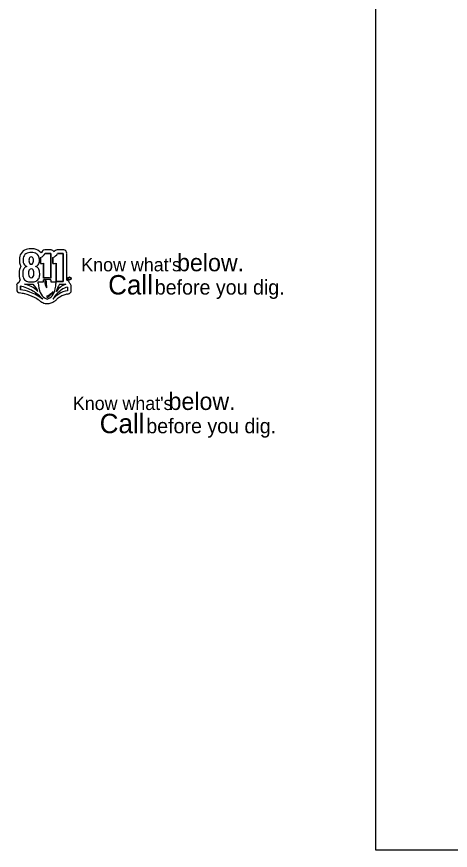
# Model space of a CAD drawing. Extents: x 837 to 1117, y 1316 to 1424.
# Drawn here: x 836.58 to 842.85, y 1398.24 to 1410.3 of the extents above; entities that cross this region are included whole.
import ezdxf

# ---------------------------------------------------------------- set-up
doc = ezdxf.new("R2010")
doc.units = 0
doc.layers.add('0 (Construction)', color=7, linetype='Continuous')
doc.layers.add('Call811-black', color=7, linetype='Continuous')

msp = doc.modelspace()

# ---------------------------------------------------------------- linework, layer by layer
at = {"layer": '0 (Construction)'}
msp.add_lwpolyline([(841.77, 1422.24), (877.77, 1422.24), (877.77, 1398.24), (841.77, 1398.24)], close=True, dxfattribs=at)
at = {"layer": 'Call811-black'}
for p, q in [((836.95, 1406.908), (836.929, 1406.881)), ((837.074, 1406.925), (836.987, 1406.925)), ((836.988, 1406.871), (837.069, 1406.871)), ((837.069, 1406.871), (837.069, 1406.514)), ((837.119, 1406.895), (837.118, 1406.895)), ((837.257, 1406.925), (837.163, 1406.925)), ((837.168, 1406.871), (837.249, 1406.871)), ((837.249, 1406.871), (837.249, 1406.465)), ((837.303, 1406.485), (837.303, 1406.874)), ((836.924, 1406.726), (836.924, 1406.813)), ((836.966, 1406.514), (836.966, 1406.732)), ((837.101, 1406.726), (837.101, 1406.813)), ((837.146, 1406.465), (837.146, 1406.732)), ((836.966, 1406.464), (836.966, 1406.49)), ((837.069, 1406.49), (837.069, 1406.464)), ((836.577, 1406.414), (836.577, 1406.35)), ((836.63, 1406.347), (836.63, 1406.4)), ((836.69, 1406.428), (836.813, 1406.428)), ((836.89, 1406.44), (836.89, 1406.464)), ((836.89, 1406.464), (836.966, 1406.464)), ((837.069, 1406.464), (837.144, 1406.464)), ((837.144, 1406.464), (837.144, 1406.44)), ((837.249, 1406.465), (837.146, 1406.465)), ((837.196, 1406.427), (837.289, 1406.427)), ((837.313, 1406.386), (837.313, 1406.333)), ((837.367, 1406.331), (837.367, 1406.396))]:
    msp.add_line(p, q, dxfattribs=at)
for points in [[(836.95, 1406.908), (836.929, 1406.881)], [(837.074, 1406.925), (836.987, 1406.925)], [(837.069, 1406.514), (837.069, 1406.871), (836.988, 1406.871)], [(837.119, 1406.895), (837.118, 1406.895)], [(837.146, 1406.465), (837.249, 1406.465), (837.249, 1406.871), (837.168, 1406.871)], [(837.257, 1406.925), (837.163, 1406.925)], [(837.303, 1406.485), (837.303, 1406.874)], [(836.924, 1406.813), (836.924, 1406.726)], [(836.966, 1406.732), (836.966, 1406.514)], [(837.101, 1406.813), (837.101, 1406.726)], [(837.146, 1406.732), (837.146, 1406.465)], [(836.89, 1406.44), (836.89, 1406.464), (836.966, 1406.464), (836.966, 1406.49)], [(837.069, 1406.49), (837.069, 1406.464), (837.144, 1406.464), (837.144, 1406.44)], [(836.577, 1406.414), (836.577, 1406.35)], [(836.63, 1406.4), (836.63, 1406.347)], [(836.69, 1406.428), (836.813, 1406.428)], [(837.196, 1406.427), (837.289, 1406.427)], [(837.313, 1406.386), (837.313, 1406.333)], [(837.367, 1406.331), (837.367, 1406.396)], [(837.017, 1406.237), (837.018, 1406.261)]]:
    msp.add_lwpolyline(points, dxfattribs=at)
for radius in [0.0224, 0.0224, 0.0191, 0.0191]:
    msp.add_circle((837.341, 1406.511), radius, dxfattribs=at)
for centre, radius, start, end in [((836.76, 1406.796), 0.143, 99.999, 175.1926), ((836.76, 1406.796), 0.143, 99.999, 175.1926), ((836.763, 1406.795), 0.0905, 126.3161, 173.2477), ((836.763, 1406.795), 0.0905, 126.3161, 173.2477), ((836.783, 1406.746), 0.142, 87.8118, 121.4594), ((836.783, 1406.746), 0.142, 87.8118, 121.4594), ((836.788, 1406.622), 0.318, 82.8327, 99.5813), ((836.788, 1406.622), 0.318, 82.8327, 99.5813), ((836.792, 1406.747), 0.141, 58.4897, 91.5654), ((836.792, 1406.747), 0.141, 58.4897, 91.5654), ((836.811, 1406.79), 0.149, 37.4108, 83.4439), ((836.811, 1406.79), 0.149, 37.4108, 83.4439), ((836.813, 1406.795), 0.0905, 6.7523, 53.6839), ((836.813, 1406.795), 0.0905, 6.7523, 53.6839), ((836.866, 1406.941), 0.141, 294.2543, 330.2691), ((836.866, 1406.941), 0.141, 294.2543, 330.2691), ((836.987, 1406.877), 0.0484, 90.4592, 139.5917), ((836.987, 1406.877), 0.0484, 90.4592, 139.5917), ((837.07, 1406.872), 0.0532, 25.4835, 85.607), ((837.07, 1406.872), 0.0532, 25.4835, 85.607), ((837.043, 1406.947), 0.147, 293.5734, 328.8767), ((837.043, 1406.947), 0.147, 293.5734, 328.8767), ((837.167, 1406.871), 0.0538, 94.7078, 153.6211), ((837.167, 1406.871), 0.0538, 94.7078, 153.6211), ((837.25, 1406.872), 0.0534, 2.8738, 82.3381), ((837.25, 1406.872), 0.0534, 2.8738, 82.3381), ((836.871, 1406.773), 0.255, 172.2103, 188.1816), ((836.871, 1406.773), 0.255, 172.2103, 188.1816), ((836.75, 1406.756), 0.133, 188.1816, 212.2335), ((836.75, 1406.756), 0.133, 188.1816, 212.2335), ((836.832, 1406.773), 0.163, 168.7247, 190.4792), ((836.832, 1406.773), 0.163, 168.7247, 190.4792), ((836.742, 1406.753), 0.07, 187.8977, 254.9735), ((836.742, 1406.753), 0.07, 187.8977, 254.9735), ((836.886, 1406.771), 0.131, 172.09, 185.2177), ((836.886, 1406.771), 0.131, 172.09, 185.2177), ((836.823, 1406.762), 0.0679, 181.9453, 206.7716), ((836.823, 1406.762), 0.0679, 181.9453, 206.7716), ((836.817, 1406.781), 0.0618, 152.1584, 172.0655), ((836.817, 1406.781), 0.0618, 152.1584, 172.0655), ((836.786, 1406.797), 0.0271, 87.8996, 151.6932), ((836.786, 1406.797), 0.0271, 87.8996, 151.6932), ((836.788, 1406.745), 0.0292, 209.2686, 270.3024), ((836.788, 1406.745), 0.0292, 209.2686, 270.3024), ((836.789, 1406.797), 0.0272, 28.3588, 93.3211), ((836.789, 1406.797), 0.0272, 28.3588, 93.3211), ((836.787, 1406.745), 0.0293, 271.4639, 330.7182), ((836.787, 1406.745), 0.0293, 271.4639, 330.7182), ((836.758, 1406.781), 0.0618, 7.9345, 27.8416), ((836.758, 1406.781), 0.0618, 7.9345, 27.8416), ((836.752, 1406.762), 0.0679, 333.2284, 358.0547), ((836.752, 1406.762), 0.0679, 333.2284, 358.0547), ((836.69, 1406.771), 0.131, 354.7823, 7.91), ((836.69, 1406.771), 0.131, 354.7823, 7.91), ((836.834, 1406.753), 0.07, 285.0265, 352.1023), ((836.834, 1406.753), 0.07, 285.0265, 352.1023), ((836.743, 1406.773), 0.163, 349.5208, 11.2753), ((836.743, 1406.773), 0.163, 349.5208, 11.2753), ((836.934, 1406.815), 0.0887, 263.562, 290.9659), ((836.934, 1406.815), 0.0887, 263.562, 290.9659), ((837.112, 1406.825), 0.0988, 263.8986, 289.847), ((837.112, 1406.825), 0.0988, 263.8986, 289.847), ((836.79, 1406.592), 0.178, 148.69, 179.574), ((836.79, 1406.592), 0.178, 148.69, 179.574), ((836.879, 1406.575), 0.215, 173.4284, 191.4963), ((836.879, 1406.575), 0.215, 173.4284, 191.4963), ((836.77, 1406.598), 0.103, 145.6767, 179.0533), ((836.77, 1406.598), 0.103, 145.6767, 179.0533), ((836.748, 1406.612), 0.0779, 108.4812, 145.0863), ((836.748, 1406.612), 0.0779, 108.4812, 145.0863), ((836.904, 1406.588), 0.156, 172.09, 185.2177), ((836.904, 1406.588), 0.156, 172.09, 185.2177), ((836.822, 1406.599), 0.0737, 152.1584, 172.0655), ((836.822, 1406.599), 0.0737, 152.1584, 172.0655), ((836.786, 1406.618), 0.0323, 87.8996, 151.6932), ((836.786, 1406.618), 0.0323, 87.8996, 151.6932), ((836.789, 1406.618), 0.0324, 28.3588, 93.3211), ((836.789, 1406.618), 0.0324, 28.3588, 93.3211), ((836.752, 1406.599), 0.0737, 7.9345, 27.8416), ((836.752, 1406.599), 0.0737, 7.9345, 27.8416), ((836.67, 1406.588), 0.156, 354.7823, 7.91), ((836.67, 1406.588), 0.156, 354.7823, 7.91), ((836.827, 1406.612), 0.0779, 34.9137, 71.5188), ((836.827, 1406.612), 0.0779, 34.9137, 71.5188), ((836.806, 1406.598), 0.103, 0.9467, 34.3233), ((836.806, 1406.598), 0.103, 0.9467, 34.3233), ((836.696, 1406.575), 0.215, 348.5037, 6.5716), ((836.696, 1406.575), 0.215, 348.5037, 6.5716), ((836.837, 1406.577), 0.226, 175.7868, 203.0663), ((836.837, 1406.577), 0.226, 175.7868, 203.0663), ((836.65, 1406.456), 0.0386, 122.909, 178.0418), ((836.65, 1406.456), 0.0386, 122.909, 178.0418), ((836.762, 1406.558), 0.0963, 195.5875, 233.3016), ((836.762, 1406.558), 0.0963, 195.5875, 233.3016), ((836.771, 1406.581), 0.12, 236.207, 265.1802), ((836.771, 1406.581), 0.12, 236.207, 265.1802), ((836.829, 1406.576), 0.0809, 181.9453, 206.7716), ((836.829, 1406.576), 0.0809, 181.9453, 206.7716), ((836.788, 1406.557), 0.0348, 209.2686, 270.3024), ((836.788, 1406.557), 0.0348, 209.2686, 270.3024), ((836.787, 1406.557), 0.0349, 271.4639, 330.7182), ((836.787, 1406.557), 0.0349, 271.4639, 330.7182), ((836.804, 1406.581), 0.12, 274.8198, 303.793), ((836.804, 1406.581), 0.12, 274.8198, 303.793), ((836.745, 1406.576), 0.0809, 333.2284, 358.0547), ((836.745, 1406.576), 0.0809, 333.2284, 358.0547), ((836.813, 1406.558), 0.0963, 306.6984, 344.4125), ((836.813, 1406.558), 0.0963, 306.6984, 344.4125), ((836.989, 1406.466), 0.0538, 98.3212, 116.1927), ((836.989, 1406.466), 0.0538, 98.3212, 116.1927), ((836.989, 1406.441), 0.0538, 98.3212, 116.1927), ((836.989, 1406.441), 0.0538, 98.3212, 116.1927), ((837.014, 1406.326), 0.196, 88.3567, 99.6507), ((837.014, 1406.326), 0.196, 88.3567, 99.6507), ((837.014, 1406.301), 0.196, 88.3567, 99.6507), ((837.014, 1406.301), 0.196, 88.3567, 99.6507), ((836.998, 1406.441), 0.0372, 82.0234, 112.2206), ((837.179, 1406.473), 0.195, 179.2441, 210.2904), ((837.591, 1406.468), 0.588, 179.0296, 189.1158), ((837.022, 1406.336), 0.186, 80.2121, 90.547), ((837.022, 1406.336), 0.186, 80.2121, 90.547), ((837.022, 1406.312), 0.186, 80.2121, 90.547), ((837.022, 1406.312), 0.186, 80.2121, 90.547), ((837.046, 1406.466), 0.0538, 63.8073, 81.6788), ((837.046, 1406.466), 0.0538, 63.8073, 81.6788), ((837.046, 1406.441), 0.0538, 63.8073, 81.6788), ((837.046, 1406.441), 0.0538, 63.8073, 81.6788), ((837.287, 1406.424), 0.0631, 53.7627, 75.1967), ((837.287, 1406.424), 0.0631, 53.7627, 75.1967), ((837.285, 1406.43), 0.0594, 7.3834, 48.7359), ((837.285, 1406.43), 0.0594, 7.3834, 48.7359), ((836.63, 1406.407), 0.0539, 110.5293, 173.0158), ((836.63, 1406.407), 0.0539, 110.5293, 173.0158), ((836.534, 1405.883), 0.525, 57.9733, 79.5163), ((836.534, 1405.883), 0.525, 57.9733, 79.5163), ((836.595, 1406.028), 0.412, 62.33, 76.6551), ((836.595, 1406.028), 0.412, 62.33, 76.6551), ((836.786, 1406.646), 0.186, 262.4451, 271.0167), ((836.786, 1406.646), 0.186, 262.4451, 271.0167), ((836.645, 1406.096), 0.329, 43.0467, 64.4523), ((836.645, 1406.096), 0.329, 43.0467, 64.4523), ((836.79, 1406.64), 0.18, 269.5148, 277.6277), ((836.79, 1406.64), 0.18, 269.5148, 277.6277), ((836.637, 1406.233), 0.263, 19.3184, 47.9077), ((836.637, 1406.233), 0.263, 19.3184, 47.9077), ((837.254, 1406.442), 0.364, 180.4178, 193.2572), ((837.254, 1406.442), 0.364, 180.4178, 193.2572), ((837.119, 1406.399), 0.222, 190.4857, 218.6347), ((837.119, 1406.399), 0.222, 190.4857, 218.6347), ((836.916, 1406.399), 0.222, 321.3653, 349.5143), ((836.916, 1406.399), 0.222, 321.3653, 349.5143), ((836.78, 1406.442), 0.364, 346.7428, 359.5822), ((836.78, 1406.442), 0.364, 346.7428, 359.5822), ((837.361, 1406.189), 0.249, 106.8433, 148.53), ((837.428, 1406.262), 0.285, 144.6348, 168.4777), ((837.361, 1406.189), 0.249, 106.8433, 148.53), ((837.428, 1406.262), 0.285, 144.6348, 168.4777), ((837.354, 1406.176), 0.214, 100.9877, 126.326), ((837.354, 1406.176), 0.214, 100.9877, 126.326), ((837.317, 1406.396), 0.0499, 0.2357, 57.1812), ((837.317, 1406.396), 0.0499, 0.2357, 57.1812), ((836.63, 1406.353), 0.0528, 183.4717, 256.8514), ((836.63, 1406.353), 0.0528, 183.4717, 256.8514), ((836.197, 1403.662), 2.672, 79.3174, 80.9479), ((836.197, 1403.662), 2.672, 79.3174, 80.9479), ((836.579, 1405.816), 0.533, 69.1311, 84.5007), ((836.579, 1405.816), 0.533, 69.1311, 84.5007), ((836.56, 1405.703), 0.6, 62.6567, 77.1974), ((836.56, 1405.703), 0.6, 62.6567, 77.1974), ((836.558, 1405.723), 0.627, 50.9726, 70.3844), ((836.558, 1405.723), 0.627, 50.9726, 70.3844), ((836.503, 1405.819), 0.597, 41.0274, 58.6813), ((836.503, 1405.819), 0.597, 41.0274, 58.6813), ((835.849, 1404.617), 1.896, 56.1356, 58.6515), ((835.849, 1404.617), 1.896, 56.1356, 58.6515), ((837.061, 1406.351), 0.147, 217.9711, 252.8236), ((837.061, 1406.351), 0.147, 217.9711, 252.8236), ((836.932, 1406.414), 0.196, 295.7354, 319.9002), ((836.974, 1406.351), 0.147, 287.1764, 322.0289), ((836.974, 1406.351), 0.147, 287.1764, 322.0289), ((836.988, 1406.379), 0.122, 284.3512, 313.9705), ((836.825, 1406.559), 0.365, 312.7475, 319.6368), ((837.01, 1406.353), 0.0975, 318.3348, 342.4149), ((837.466, 1405.999), 0.423, 124.3323, 149.8558), ((837.466, 1405.999), 0.423, 124.3323, 149.8558), ((837.385, 1405.966), 0.376, 122.1554, 139.2439), ((837.385, 1405.966), 0.376, 122.1554, 139.2439), ((837.382, 1405.96), 0.335, 122.9567, 131.4897), ((837.382, 1405.96), 0.335, 122.9567, 131.4897), ((837.354, 1406.033), 0.302, 97.6832, 123.9821), ((837.354, 1406.033), 0.302, 97.6832, 123.9821), ((837.36, 1405.996), 0.293, 110.3424, 123.2327), ((837.36, 1405.996), 0.293, 110.3424, 123.2327), ((837.371, 1405.951), 0.339, 99.6589, 109.4788), ((837.371, 1405.951), 0.339, 99.6589, 109.4788), ((837.306, 1406.355), 0.0698, 276.8288, 293.6655), ((837.306, 1406.355), 0.0698, 276.8288, 293.6655), ((837.316, 1406.339), 0.0518, 290.7825, 351.1469), ((837.316, 1406.339), 0.0518, 290.7825, 351.1469), ((837.048, 1406.377), 0.234, 232.4217, 246.1444), ((837.048, 1406.377), 0.234, 232.4217, 246.1444), ((837.017, 1406.295), 0.147, 244.4852, 271.9359), ((837.017, 1406.295), 0.147, 244.4852, 271.9359), ((837.022, 1406.331), 0.182, 269.938, 287.1165), ((837.022, 1406.331), 0.182, 269.938, 287.1165), ((837.002, 1406.354), 0.21, 290.4356, 305.7025), ((837.002, 1406.354), 0.21, 290.4356, 305.7025), ((836.928, 1406.466), 0.345, 304.793, 312.2432), ((836.928, 1406.466), 0.345, 304.793, 312.2432)]:
    msp.add_arc(centre, radius, start, end, dxfattribs=at)

# ---------------------------------------------------------------- texts
for s, height, p in [('below.', 0.2509, (838.897, 1406.615)), ("Know what's", 0.19301, (837.512, 1406.614)), ('R', 0.0236, (837.33, 1406.5)), ('Call', 0.281, (837.901, 1406.279)), ('before you dig.', 0.21231, (838.575, 1406.278)), ("Know what's", 0.19301, (837.39, 1404.608)), ('below.', 0.2509, (838.774, 1404.609)), ('Call', 0.281, (837.778, 1404.273)), ('before you dig.', 0.21231, (838.452, 1404.272))]:
    msp.add_text(s, height=height, dxfattribs=at).set_placement(p)

doc.saveas('drawing.dxf')
